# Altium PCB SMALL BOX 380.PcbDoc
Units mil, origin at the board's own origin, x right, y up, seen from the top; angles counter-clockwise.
Board outline 6000 x 4000 mil, 2 copper layers (Top Layer, Bottom Layer); 64 components, 32 nets, 216 pads, 52 vias.
Unrouted connection lines stored in the file: 8.
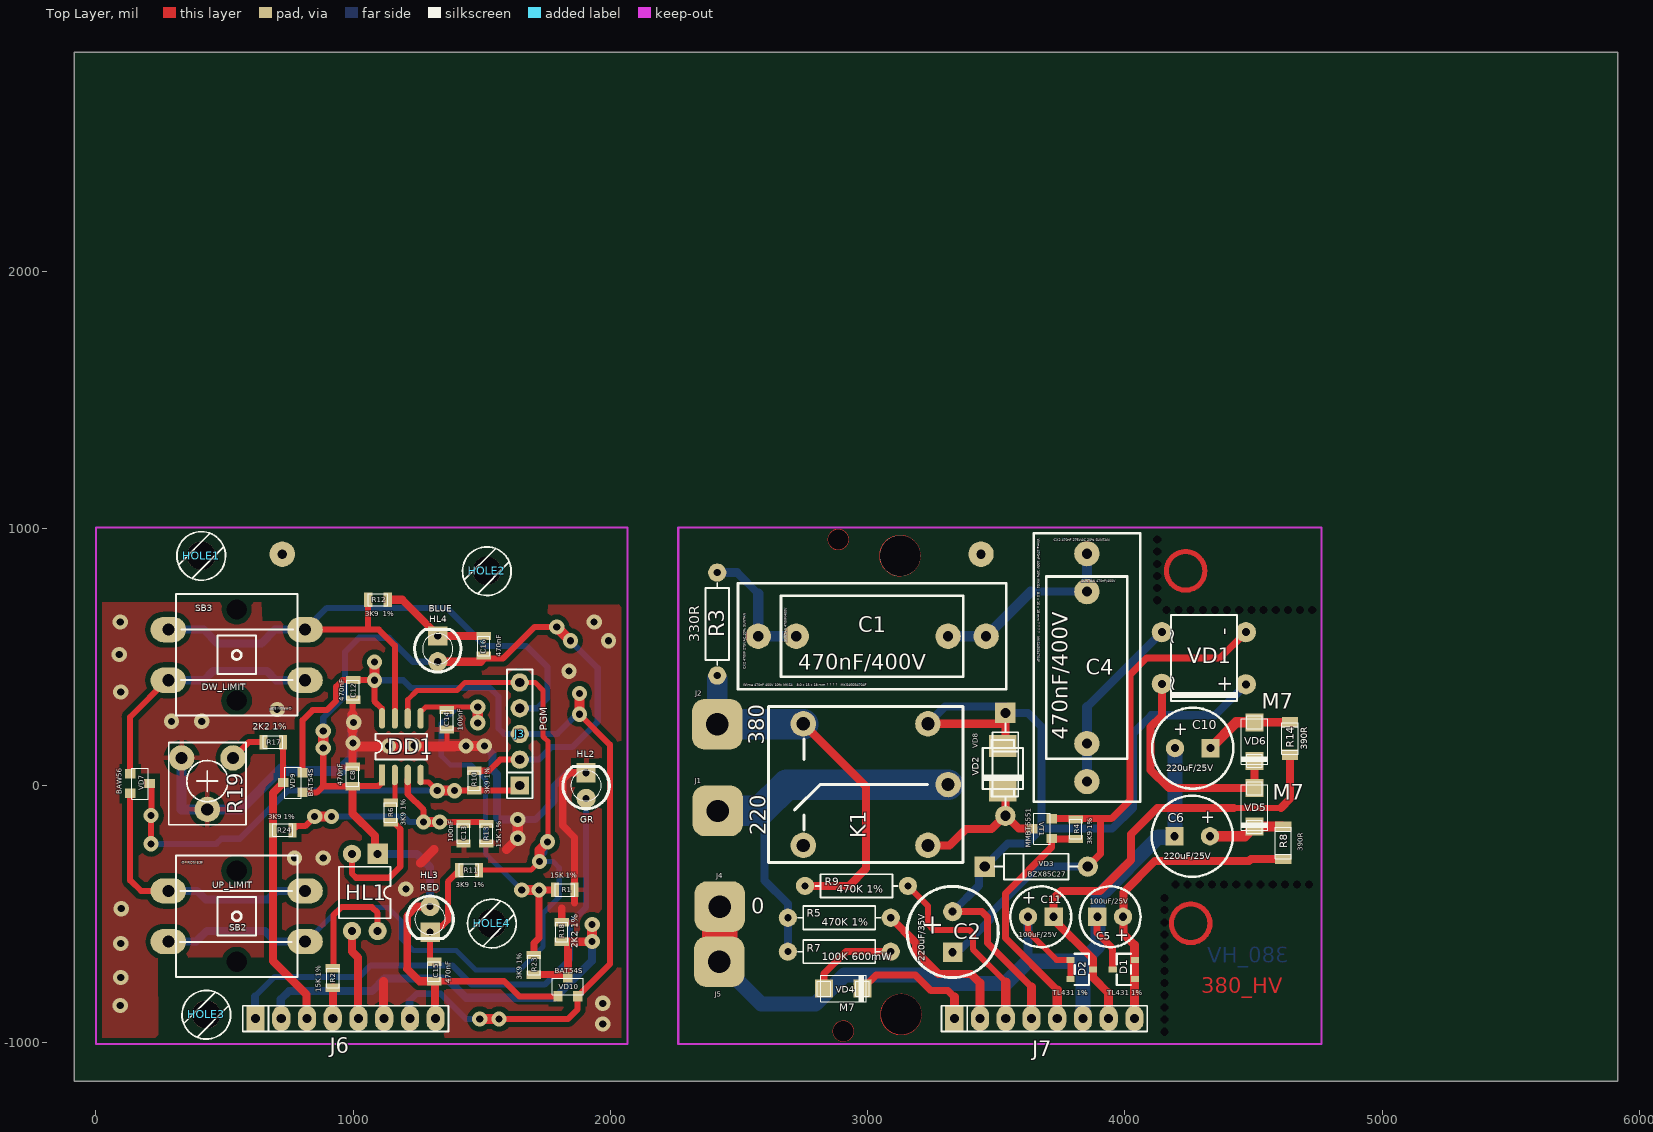
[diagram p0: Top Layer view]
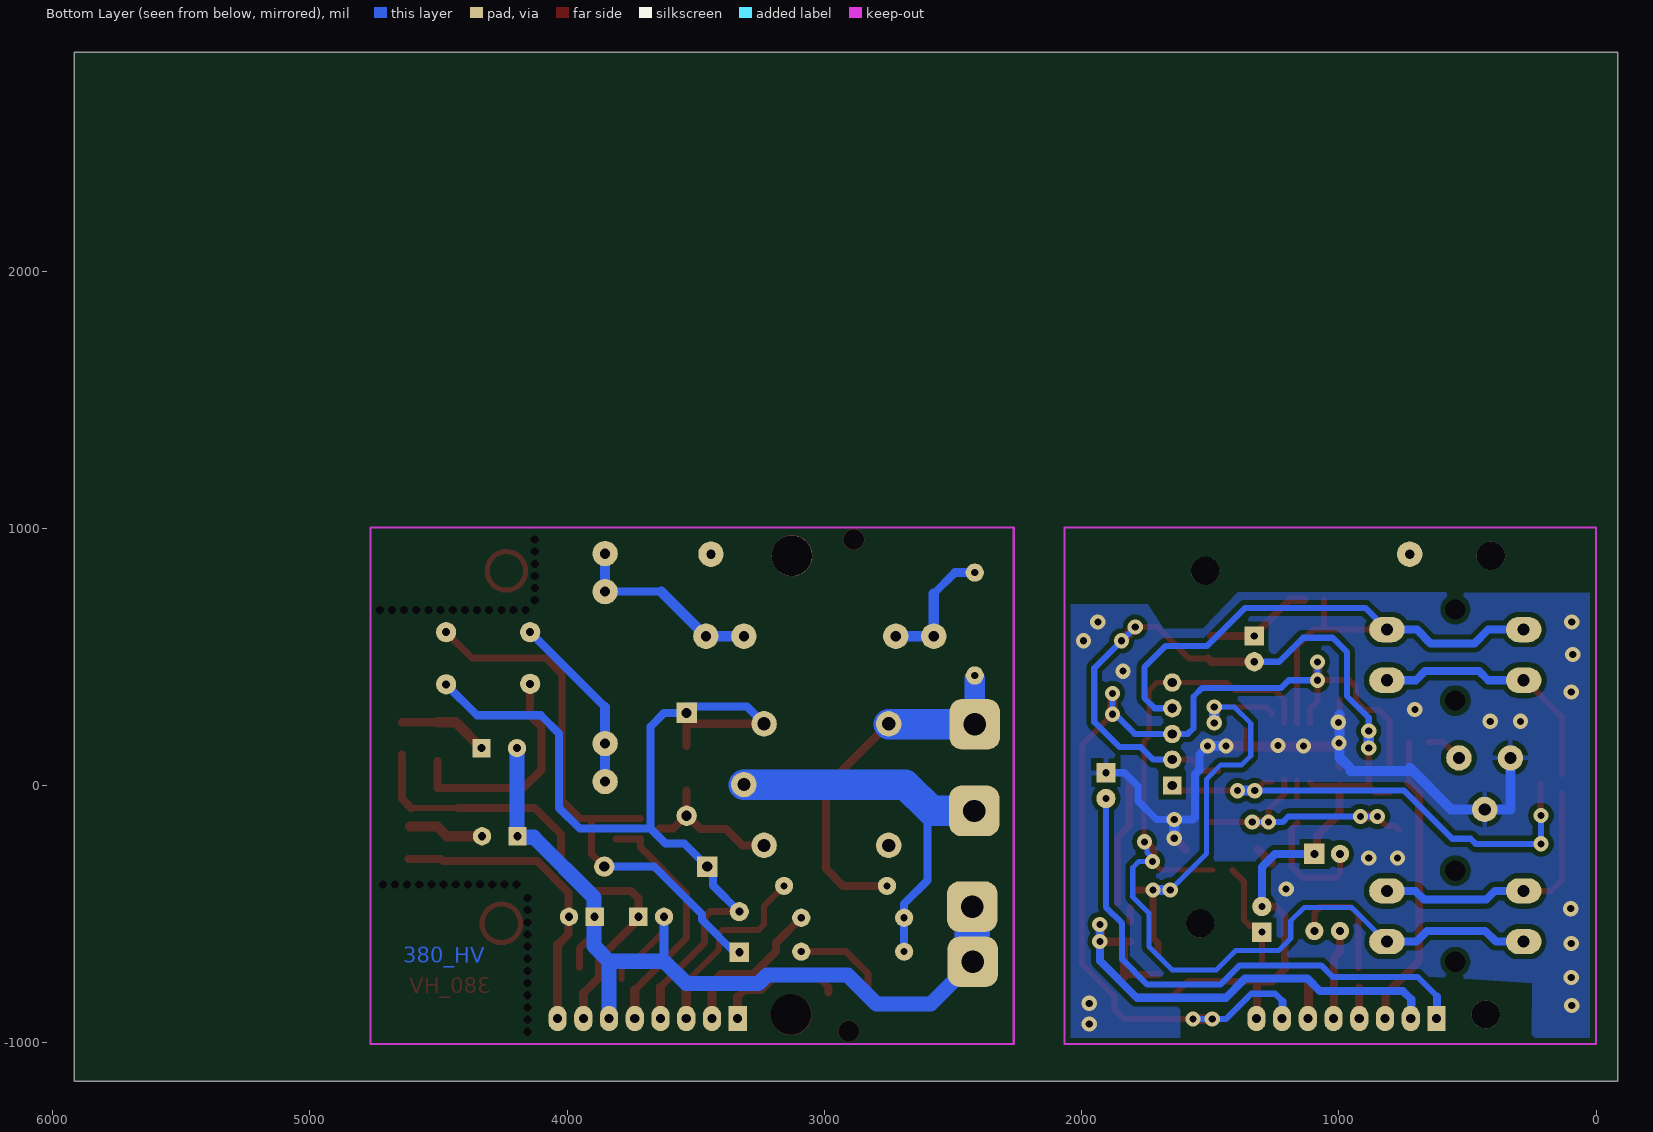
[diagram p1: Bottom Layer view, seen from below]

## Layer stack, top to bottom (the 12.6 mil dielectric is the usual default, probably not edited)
Top Layer: signal copper 1.4
Dielectric: dielectric 12.6, FR-4, Dk 4.8
Bottom Layer: signal copper 1.4

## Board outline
-84.06,-1149.25 5915.94,-1149.25 5915.94,2850.75 -84.06,2850.75

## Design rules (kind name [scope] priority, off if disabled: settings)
Clearance [All] p1: gap=19.68
ComponentClearance [All] p1: gap=15.75 collisioncheckmode=3 verticalgap=10 showdistances=TRUE
HoleSize [All] p1: absolutevalues=TRUE maxlimit=177.17 minlimit=27.56 maxpercent=80.000 minpercent=20.000
HoleToHoleClearance [All] p1: gap=15.75 allowstackedmicrovias=FALSE
PlaneConnect [All] p1: planeconnectstyle=Relief reliefexpansion=20 reliefentries=4 reliefconductorwidth=19.68 reliefairgap=10
PolygonConnect PolygonConnect_Vias [All vs isVia] p1: connectstyle=Direct reliefconductorwidth=13.78 reliefentries=4 polygonreliefangle="90 Angle"
PolygonConnect [All] p2: connectstyle=Relief reliefconductorwidth=19.68 reliefentries=4 polygonreliefangle="90 Angle"
RoomDefinition "SMALL BOX 380" [InComponentClass('SMALL BOX 380')] p1: confinementstyle=ConfineOut formatcopy=TRUE lockcomponents=FALSE outline -59.06,-1023.62 23.62,-1023.62 23.62,-1047.24 -59.06,-1047.24
RoutingVias [All] p1: holewidth=31.5 width=62.99 viastyle="Through Hole" minholewidth=27.56 minwidth=59.06 maxholewidth=35.43 maxwidth=66.93
SilkToSilkClearance [All] p1 off: silktosilkclearance=10
SilkscreenOverComponentPads [All] p1 off: minsilkscreentomaskgap=10
SolderMaskExpansion [All] p1: expansion=4
Width [All] p1: maxlimit=196.85 minlimit=19.68 preferedwidth=19.68 minimp=50.000000 maximp=50.000000 favimp=50.000000
22 further rules are at their usual default settings.

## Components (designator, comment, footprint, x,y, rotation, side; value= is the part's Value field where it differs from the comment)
C1 "470nF/400V" "C RM15+22,5" 3017.72,580.71 r0 top
C2 "220uF/35V" C_POL9X4 3330.71,-568.9 r270 top
C4 "470nF/400V" "C RM15+22,5" 3852.36,458.66 r270 top
C5 "100uF/25V" C_POL_6 3942.91,-509.84 r180 top
C6 "220uF/25V" C_POL_8 4261.81,-196.85 r180 top
C8 "470nF" 0805_STS 998.03,35.43 r90 top
C10 "220uF/25V" C_POL_8 4263.78,145.67 r0 top
C11 "100uF/25V" C_POL_6 3673.23,-509.84 r0 top
C12 "470nF" 0805_STS 1000,372.05 r90 top
C13 "100nF" 0805_STS 1429.13,-187.01 r270 top
C14 "100nF" 0805_STS 1364.17,255.91 r270 top
C15 "470nF" 0805_STS 1314.96,-722.44 r90 top
C16 "470nF" 0805_STS 1507.87,543.31 r90 top
D1 "TL431 1%" SOT-23 3996.06,-714.57 r90 top
D2 "TL431 1%" SOT-23 3832.68,-714.57 r270 top
DD1 "PIC12F1822_380_protect_1" SO-8 1112.2,41.34 r90 top
HL1 "OPTO 4" DIP4 1045.28,-415.35 r180 top
HL2 "GR" LED3 1905.51,0 r90 top
HL3 "RED" LED3 1299.21,-519.68 r270 top locked
HL4 "BLUE" LED3 1328.74,531.5 r90 top locked
HOLE1 "2,8" HOLE2,8 409.45,893.7 r0 top locked
HOLE2 "2,8" HOLE2,8 1519.69,834.65 r0 top locked
HOLE3 "2,8" HOLE2,8 429.13,-889.76 r0 top locked
HOLE4 "2,8" HOLE2,8 1539.37,-535.43 r0 top locked
J1 "220" PAD2,2 2417.32,-98.43 r0 top
J2 "380" PAD2,2 2415.35,238.19 r0 top
J3 "PGM" SIP5 1647.64,200.79 r90 top
J4 "0" PAD2,2 2425.2,-470.47 r0 top
J5 "0" PAD2,2 2423.23,-685.04 r0 top
J6 "CON8" SIP8 970.47,-905.51 r0 top locked
J7 "CON8" SIP8 3687.01,-905.51 r0 top locked
K1 "RAS24" "UNI 10A" 2992.13,3.94 r180 top
R1 "15K 1%" 0805_STS 1822.83,-405.51 r180 top
R2 "15K 1%" 0805_STS 921.26,-748.03 r270 top
R3 "330R" R1/4 2415.35,627.95 r90 top
R4 "3K9 1%" 0805_STS 3809.06,-169.29 r270 top
R5 "470K 1%" R1/4 2889.76,-513.78 r0 top
R6 "3K9 1%" 0805_STS 1145.67,-104.33 r270 top
R7 "100K 600mW" R1/4 2889.76,-645.67 r0 top
R8 "390R" 1206_STS 4616.14,-222.44 r270 top
R9 "470K 1%" R1/4 2956.69,-389.76 r0 top
R10 "3K9 1%" 0805_STS 1470.47,19.68 r90 top
R11 "3K9  1%" 0805_STS 1450.79,-328.74 r0 top
R12 "3K9  1%" 0805_STS 1096.46,722.44 r180 top
R13 "15K 1%" 0805_STS 1517.72,-187.01 r90 top
R14 "390R" 1206_STS 4641.73,183.07 r270 top
R17 "2K2 1%" 0805_STS 688.98,169.29 r180 top
R18 "2K2 1%" 0805_STS 1811.02,-568.9 r270 top
R19 "220R" RT_7.5X5_2 433.07,-92.52 r90 top
R23 "3K9 1%" 0805_STS 1702.76,-696.85 r270 top
R24 "3K9 1%" 0805_STS 726.38,-173.23 r180 top
SB2 "UP_LIMIT" "BTN BIG OMRON B3F" 547.24,-507.87 r0 top locked
SB3 "DW_LIMIT" "BTN BIG OMRON B3F" 547.24,507.87 r180 top locked
VD1 "BRIDGE SQ" "BRIDGE SQ TH" 4307.09,496.06 r270 top
VD2 "SMAJ 50V" SMB 3525.59,66.93 r270 top
VD3 "BZX85C27" 1N4004 3655.51,-314.96 r180 top
VD4 "M7" SMA 2905.51,-789.37 r0 top
VD5 "M7" SMA 4503.94,-84.65 r270 top
VD6 "M7" SMA 4503.94,171.26 r270 top
VD7 "BAW56" SOT-23-STS 171.26,7.87 r270 top
VD8 "P6KE" 1N4004 3535.43,82.68 r90 top
VD9 "BAT54S" SOT-23-STS 765.75,11.81 r90 top
VD10 "BAT54S" SOT-23-STS 1834.65,-781.5 r0 top
VT1 "MMBT5551" SOT-23-STS 3677.17,-167.32 r90 top

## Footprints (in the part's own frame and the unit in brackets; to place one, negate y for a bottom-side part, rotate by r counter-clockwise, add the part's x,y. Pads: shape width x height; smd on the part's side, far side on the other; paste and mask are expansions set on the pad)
1N4004 [mil]
  round 79 hole 39.37: 1(-200,0)
  rect 79x79 hole 39.37: 2(200,0)
  silkscreen extent -160,-50 160,50
0805_STS [mil]
  rect 32x56 smd: 1(-38,0) 2(38,0)
  silkscreen extent -38,-24 38,24
1206_STS [mm]
  rect 1x1.6 smd: 1(-1.6,0) 2(1.6,0)
  silkscreen extent -1.55,-0.8 1.55,0.8
"BRIDGE SQ TH" [mm] "DFxx DB10x"
  round 2 hole 0.8: 1(-2.55,-4.15) 2(2.55,-4.15) 3(2.6,4.15) 4(-2.55,4.15)
  silkscreen extent -4.25,-3.25 4.25,3.25
"BTN BIG OMRON B3F" [mm] "От китайската дефектнотокова"
  round 1.524 hole 2: 0(0,-4.5) 0(0,4.5)
  oval 3.5x2.5 hole 1.2: 1(-6.75,2.5) 1'(6.75,2.5) 2(-6.75,-2.5) 2'(6.75,-2.5)
  silkscreen extent -6,-6 6,6
"C RM15+22,5" [mm] "За 2 кондензатора с растер 15 и 22,5мм"
  round 2.5 hole 1: 1(-11.25,0) 1'(-7.5,0) 2(7.5,0) 2'(11.25,0)
  silkscreen extent -13.25,-5.25 13.25,5.25
C_POL9X4 [mm]
  round 1.9 hole 0.8: 1(-2,0)
  rect 1.9x1.9 hole 0.8: 2(2,0)
  silkscreen extent -4.5,-4.5 4.5,4.5
C_POL_6 [mil]
  round 71 hole 31.5: 1(-50,0)
  rect 71x71 hole 31.5: 2(50,0)
  silkscreen extent -118,-118 118,118
C_POL_8 [mil]
  round 71 hole 31.5: 1(-68.9,0)
  rect 71x71 hole 31.5: 2(68.9,0)
  silkscreen extent -157,-157 157,157
DIP4 [mil]
  rect 79x79 hole 31.5: 1(-50,-150)
  round 71 hole 31.5: 2(50,-150) 3(50,150) 4(-50,150)
  silkscreen extent -100,-100 100,100
HOLE2,8 [mm] "ЗА защитата"
  round 2.8 hole 2.8 unplated: ""(0,0)
  silkscreen extent -2.4,-2.43 2.4,2.37
LED3 [mm]
  round 1.905 hole 0.7: 1(-1.27,0)
  rect 1.905x1.905 hole 0.7: 2(1.27,0)
  silkscreen extent -2.29,-2.29 1.91,2.29
PAD2,2 [mm] "За многожилна жица"
  rrect50% 5x5 hole 2.2: 1(0,0)
R1/4 [mm]
  round 1.8 hole 0.7: 1(-5.08,0) 2(5.08,0)
  silkscreen extent -4.06,-1.15 4.06,1.15
RT_7.5X5_2 [mil]
  round 99 hole 47.24: 1(200,-100) 2(0,0) 3(200,100)
  silkscreen extent -60,-150 260,150
SIP5 [mil]
  rect 71x71 hole 35.43: 1(-200,0)
  round 71 hole 35.43: 2(-100,0) 3(0,0) 4(100,0) 5(200,0)
  silkscreen extent -250,-50 250,50
SIP8 [mm]
  rect 1.8x2.5 hole 0.9: 1(-8.89,0)
  oval 1.8x2.5 hole 0.9: 2(-6.35,0) 3(-3.81,0) 4(-1.27,0) 5(1.27,0) 6(3.81,0) 7(6.35,0) 8(8.89,0)
  silkscreen extent -10.16,-1.27 10.16,1.27
SMA [mil]
  rect 70x70 smd: 1(-75,0) 2(75,0)
  silkscreen extent -100,-52 100,51
SMB [mil]
  rect 85x108 smd: 1(-87,0) 2(87,0)
  silkscreen extent -110,-79 110,78
SO-8 [mil]
  rect 80x24 smd: 1(0,0)
  oval 80x24 smd: 2(0,-50) 3(0,-100) 4(0,-150) 5(220,-150) 6(220,-100) 7(220,-50) 8(220,0)
  silkscreen extent 60,-175 160,25
SOT-23 [mm]
  rect 0.6x0.8 smd: 1(-0.95,-1.1) 2(0.95,-1.1) 3(0,1.1)
  silkscreen extent -1.55,-0.7 1.55,0.7
SOT-23-STS [mil]
  rect 36x41 smd: 1(-38,-38) 2(38,-38) 3(0,37)
  silkscreen extent -60,-32 60,32
"UNI 10A" [mm]
  round 2.515 hole 1.3: 1(-8.15,0) 2(6.15,6) 3(6.15,-6) 4(-6.15,6) 5(-6.15,-6)
  silkscreen extent -9.6,-7.7 9.6,7.7

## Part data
C1 C4: library part "C RM15+22,5"
C2 C5 C6 C10 C11: library part C-POL
C8 C12 C13 C14 C15 C16: library part C-SMD
D1 D2: library part D_ZR431, "Reference Zener Diode"
HL2 HL3 HL4: library part LED
HOLE1 HOLE2 HOLE3 HOLE4: library part HOLE
J1 J2 J4 J5: library part CON1
J3: library part CON5
K1: library part "RELAY 1GR"
R1 R2 R4 R6 R8 R10 R11 R12 R13 R14 R18 R23 R24: library part R-SMD
R3 R5 R7 R9 R17: library part R1/4
R19: library part R-TRIM
SB2 SB3: library part "SW-BUTTON A"
VD2 VD8: library part SIBAR
VD3: library part "DIODE ZENER"
VD4 VD5 VD6: library part DIODE-SMD
VD7: library part DIODE-CA
VD9 VD10: library part DIODE-DBL
VT1: library part NPN-SMD

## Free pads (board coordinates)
  round 98.43 hole 35.43: 0(724.41,899.61) 0(3440.95,899.61)
  round 157.48 hole 157.48: 0(3125.98,893.7)
  round 60 hole 157.48: 1(3129.92,-889.76)
  round 0 hole 31.5: 22(4125.98,720.47) 22(4125.98,767.72) 22(4125.98,814.96) 22(4125.98,862.2) 22(4125.98,909.45) 22(4125.98,956.69) 22(4153.54,-956.69) 22(4153.54,-909.45) 22(4153.54,-862.2) 22(4153.54,-814.96) 22(4153.54,-767.72) 22(4153.54,-720.47) 22(4153.54,-673.23) 22(4153.54,-625.98) 22(4153.54,-578.74) 22(4153.54,-531.5) 22(4153.54,-484.25) 22(4153.54,-437.01) 22(4161.42,683.07) 22(4196.85,-383.86) 22(4208.66,683.07) 22(4244.09,-383.86) 22(4255.91,683.07) 22(4291.34,-383.86) 22(4303.15,683.07) 22(4338.58,-383.86) 22(4350.39,683.07) 22(4385.83,-383.86) 22(4397.64,683.07) 22(4433.07,-383.86) 22(4444.88,683.07) 22(4480.32,-383.86) 22(4492.13,683.07) 22(4527.56,-383.86) 22(4539.37,683.07) 22(4574.8,-383.86) 22(4586.61,683.07) 22(4622.05,-383.86) 22(4633.86,683.07) 22(4669.29,-383.86) 22(4681.1,683.07) 22(4716.54,-383.86) 23(4728.35,683.07)
  round 0 hole 78.74: 53(2885.83,956.69) 53(2905.51,-954.72)

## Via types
v1: diameter 59.06, hole 27.56, Top Layer to Bottom Layer, tented both sides, 52 vias

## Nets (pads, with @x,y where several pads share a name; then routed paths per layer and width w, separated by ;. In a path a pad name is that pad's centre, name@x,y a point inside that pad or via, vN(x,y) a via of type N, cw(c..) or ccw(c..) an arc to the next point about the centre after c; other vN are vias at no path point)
220: J1.1 K1.1 R5.1 R7.1 | length 1534.6
  Bottom Layer w31.5: 2599.21,-86.61 2599.21,-368.9 2689.76,-459.45 R7.1
  Bottom Layer w118.11: J1.1 2582.68,-98.43 2685.04,3.94 K1.1
380: J2.1 K1.3 R3.1 R9.1 | length 1441.8
  Top Layer w31.5: K1.3 2994.09,-3.94 2994.09,-322.83 2927.17,-389.76 R9.1
  Bottom Layer w78.74: J2.1 R3.1@2415.35,416.14
  Bottom Layer w118.11: J2.1 K1.3@2750,238.19
C2*1: C2.1 J6.4 J7.4 K1.5 R2.2 VD1.3 VD2.1 VD3.2 VD8.2 | length 3777.4
  Top Layer w27.56: C2.1 3444.88,-490.16 3466.54,-511.81 3466.54,-612.2 3637.01,-782.68
  Top Layer w31.5: J6.4@921.26,-906.88 R2.2@921.26,-785.43 ; K1.5@3234.64,240.54 3535.43,240.54 ; VD2.1@3535.43,153.93 3535.43,240.54 ; VD8.2@3535.43,306.3 3535.43,240.54
  Top Layer w35.43: J7.4 3637.01,-782.68
  Bottom Layer w31.5: K1.5 3301.18,307.09 VD8.2@3535.43,307.09 ; C2.1 3433.07,-387.8 3433.07,-337.4 VD3.2 3544.69,-225.79 ; VD8.2 3622.83,282.68 3675.2,230.32 3675.2,-167.32 3950.79,-167.32 4031.5,-86.61 4031.5,202.76 4102.36,273.62 4350.39,273.62 VD1.3 ; 3545.28,-225.79 3618.11,-225.79 3676.57,-167.32
GND: C5.2 C6.2 C8.2 C10.1 C11.1 C12.1 C13.2 C14.2 D1.3 D2.1 D2.2 HL2.2 J4.1 J5.1 J6.6 J7.6 R1.1 R13.1 R18.1 R19.2 R19.3 | length 7850.1
  Top Layer w19.68: 1364.17,153.54 C14.2
  Top Layer w23.62: 998.03,275.59 C12.1@998.03,334.05 ; C11.1 3623.23,-566.14 3734.25,-677.17 D2.1 D2.2
  Top Layer w27.56: R18.1 1811.02,-476.38 ; 1860.83,-455.24 R1.1 1860.83,-201.39 1814.96,-155.51 1814.96,23.62 1841.34,50 HL2.2 ; C5.2@3891.73,-507.87 3891.73,-572.83 3952.76,-633.86 D1.3@3952.76,-706.69
  Top Layer w31.5: C8.2 998.03,151.57 998.03,214.57
  Top Layer w35.43: J6.6@1118.5,-907.48 1118.5,-761.42 ; 1261.81,-301.18 1314.96,-248.03 ; 1596.46,-248.03 v1(1639.76,-204.72)
  Top Layer w39.37: v1@998.03,151.57 1391.73,151.57 ; 998.03,214.57 998.03,275.59 ; 1364.17,153.54 v1(1509.84,153.54) ; v1(1639.76,-204.72) v1(1639.76,-131.89)
  Top Layer w137.8: J5.1@2425.2,-671.26 J4.1
  Bottom Layer w27.56: v1(1639.76,-131.89) 1708.66,-131.89 1781.5,-59.06 1781.5,-1.97 1833.46,50 HL2.2
  Bottom Layer w31.5: v1(1509.84,153.54) 1541.34,122.05 1541.34,62.06 1559.06,44.34 1559.06,-124.02 1566.93,-131.89 v1(1639.76,-131.89)
  Bottom Layer w35.43: 3623.62,-682.68 C11.1@3623.62,-509.84
  Bottom Layer w39.37: R19.3 333.07,-92.52 R19.2 562.99,-92.52 724.41,68.9 ; 722.44,57.09 954.72,57.09 ; 956.69,68.9 998.03,110.24 998.03,275.59 ; v1(1438.98,153.54) v1(1509.84,153.54) ; v1(1639.76,-204.72) v1(1639.76,-131.89)
  Bottom Layer w59.06: J5.1@2425.2,-687.01 2586.61,-848.43 2797.24,-848.43 2909.45,-736.22 3222.44,-736.22 3255.91,-769.68 3536.61,-769.68 3623.62,-682.68 3837.01,-682.68 ; J7.6 3837.01,-682.68 ; C6.2@4192.91,-200.79 4129.92,-200.79 3895.67,-435.04 3895.67,-624.02 3837.01,-682.68 ; C6.2@4194.88,-194.88 C10.1
  Bottom Layer w137.8: J5.1@2425.2,-687.01 J4.1
  other v1: 1970.47,-927.17 94.49,-854.33 1970.47,-846.46 96.46,-746.06 96.46,-614.17 98.43,-478.35 1204.72,-401.57 771.65,-281.5 883.86,-281.5 1137.8,153.54 1236.22,155.51 1000,165.35 1001.97,246.06 293.31,250 411.42,250 704.72,295.28 96.46,364.17 1838.58,444.88 90.55,509.84 1992.13,562.99 94.49,635.83 1937.01,635.83
HL1*3: HL1.3 J6.5 J7.5 R4.2 VT1.1 | length 1287.8
  Top Layer w27.56: VT1.1 3715.17,-239.56 3535.43,-419.29 3535.43,-592.52 3737.01,-794.09 ; VT1.1@3730.91,-207.29 R4.2
  Top Layer w31.5: HL1.3 995.28,-644.88 1018.9,-668.5 J6.5@1018.9,-907.09
  Top Layer w35.43: J7.5 3737.01,-794.09
HL2*1: HL2.1 J6.1 J7.1 VD4.2 | length 2595.4
  Top Layer w27.56: VD4.2@2984.45,-785.24 3033.46,-736.22 3185.04,-736.22 3246.06,-797.24 3312.99,-797.24 3337.01,-821.26
  Top Layer w31.5: VD4.2@2984.45,-803.15 VD4.2@2984.45,-785.24
  Top Layer w35.43: J7.1 3337.01,-821.26
  Bottom Layer w23.62: 618.5,-819.29 693.7,-744.09 1023.62,-744.09 1068.9,-698.82 1385.83,-698.82 1460.63,-773.62 1744.09,-773.62 1842.52,-675.2 1842.52,-535.43 1905.51,-472.44 HL2.1
  Bottom Layer w31.5: J6.1@618.5,-907.48 618.5,-819.29
NetC1_1: C1.1 C1.1' R3.2 | length 506.4
  Bottom Layer w31.5: 2492.91,827.95 2574.8,746.06
  Bottom Layer w35.43: R3.2 2492.91,827.95
  Bottom Layer w39.37: 2574.8,746.06 C1.1 C1.1'
NetC1_2: C1.2 C1.2' C4.1 C4.1' | length 758.8
  Bottom Layer w31.5: 3633.86,753.94 C4.1'
  Bottom Layer w39.37: C1.2 C1.2' 3633.86,753.94 ; C4.1' C4.1
NetC2_2: C2.2 R4.1 VD1.4 VD3.1 VT1.2 | length 2235.4
  Top Layer w27.56: VT1.2@3715.17,-127.95 3948.82,-127.95 4019.69,-57.09 4019.69,431.1 4084.65,496.06 4370.08,496.06 VD1.4 ; VD3.1 3905.51,-264.96 3905.51,-127.95
  Top Layer w31.5: VD3.1 VD3.1@3855.51,-303.94
  Bottom Layer w31.5: C2.2 3350.39,-647.64 3476.38,-521.65 3476.38,-500 3661.42,-314.96 VD3.1
NetC4_2: C4.2 C4.2' VD1.1 | length 701.4
  Bottom Layer w31.5: 3852.36,305.12 VD1.1
  Bottom Layer w39.37: C4.2' C4.2 3852.36,305.12
NetC6_1: C6.1 R8.1 VD5.2 | length 294.7
  Top Layer w39.37: C6.1 4466.73,-196.85 VD5.2 R8.1@4610.04,-159.65
NetC10_2: C10.2 R14.1 VD6.1 | length 350.7
  Top Layer w31.5: VD6.1 R14.1@4641.73,246.26
  Top Layer w39.37: C10.2 4433.27,246.26 VD6.1
NetC13_1: C13.1 DD1.3 R13.2 R24.1 | length 1087.3
  Top Layer w23.62: R24.1 780.13,-157.48 812.99,-157.48 v1(850.39,-120.08) ; DD1.3@1212.2,23.62 1212.2,-33.07 1273.62,-94.49 v1(1273.62,-141.73) ; v1(1336.61,-141.73) R13.2@1501.97,-141.73
  Top Layer w39.37: v1(850.39,-120.08) v1(915.35,-120.08) ; v1(1273.62,-141.73) v1(1336.61,-141.73)
  Bottom Layer w23.62: v1(850.39,-120.08) 1196.85,-120.08 1218.5,-141.73 v1(1273.62,-141.73) v1(1336.61,-141.73)
NetC14_1: C14.1 DD1.5 R1.2 R23.1 | length 1814.6
  Top Layer w19.68: DD1.5@1261.81,273.62 1261.81,285.43 1281.5,305.12 v1(1484.25,305.12)
  Top Layer w27.56: R23.1 1702.76,-612.2 1722.44,-592.52 v1(1722.44,-405.51) R1.2
  Top Layer w39.37: v1(1484.25,244.09) v1(1484.25,305.12) ; v1(1655.51,-405.51) v1(1722.44,-405.51)
  Bottom Layer w19.68: v1(1484.25,305.12) 1405.51,305.12 1342.52,242.13 1342.52,116.14 1377.95,80.71 1458.66,80.71 1513.78,25.59 1513.78,-263.78 v1(1655.51,-405.51)
  Bottom Layer w39.37: v1(1484.25,244.09) v1(1484.25,305.12) ; v1(1655.51,-405.51) v1(1722.44,-405.51)
NetC15_2: C15.2 HL3.2 R11.1 | length 402.9
  Top Layer w23.62: C15.2@1299.21,-678.54 HL3.2 ; HL3.2@1318.9,-545.28 1346.46,-545.28 1368.21,-523.52 1368.21,-441.11 1368.11,-441.01 1368.11,-374.02 R11.1@1397.64,-344.49 ; R11.1 1397.64,-343.89 R11.1@1397.64,-344.49 ; R11.1@1414.07,-330.02 1399.61,-344.49 R11.1@1397.64,-344.49
NetC16_2: C16.2 HL4.2 R12.1 | length 424.4
  Top Layer w31.5: R12.1 1190.95,722.44 1330.71,582.68 HL4.2@1327.56,582.68 ; HL4.2 C16.2@1495.87,581.5
NetDD1_2: DD1.2 R6.1 | length 73.4
  Top Layer w19.68: 1162.2,-49.8 DD1.2@1162.2,23.62
NetHL1_2: HL1.2 R6.2 | length 466.6
  Top Layer w23.62: HL1.2 995.28,-341.73 1011.81,-358.27 1139.76,-358.27 1183.07,-314.96 1183.07,-167.92 R6.2@1161.42,-146.27
NetHL1_4: HL1.4 R2.1 | length 469.6
  Top Layer w23.62: R2.1@923.23,-708.66 923.23,-503.94 954.72,-472.44 1072.83,-472.44 1095.28,-494.88 HL1.4
NetK1_4: K1.4 VD2.2 VD8.1 VT1.3 | length 571.2
  Top Layer w31.5: K1.4 3318.9,-232.28 3381.89,-169.29 3481.5,-169.29 VD8.1@3535.43,-115.35 ; VD2.2@3535.43,-20.07 VD8.1@3535.43,-115.35 ; VT1.3 3587.4,-167.32 VD8.1@3535.43,-115.35
NetR7_2: R7.2 VD4.1 | length 353.3
  Top Layer w27.56: VD4.1 2830.51,-730.51 2915.35,-645.67 R7.2
NetR17_2: R17.2 R19.1 | length 143.5
  Top Layer w23.62: R19.1 594.88,169.29 R17.2
NetSB2_1: SB2.1 SB2.1' VD7.2 | length 1062.4
  Top Layer w23.62: 133.26,-368.11 VD7.2 ; 133.56,-367.81 175.2,-409.45 SB2.1
  Bottom Layer w31.5: SB2.1 393.7,-409.45 427.17,-442.91 669.29,-442.91 702.76,-409.45 SB2.1'
NetSB3_1: SB3.1 SB3.1' VD7.1 | length 991.3
  Top Layer w23.62: 132.57,266.43 SB3.1'@281.5,415.35 ; VD7.1 133.26,265.75
  Bottom Layer w31.5: SB3.1' 419.29,409.45 454.72,444.88 665.35,444.88 700.79,409.45 SB3.1
NetVD1_2: VD1.2 VD5.1 VD6.2 | length 891.3
  Top Layer w31.5: VD1.2 4143.7,271.65 4100.39,228.35 4100.39,61.02 4171.06,-9.65 VD5.1 VD6.2
PGC: DD1.6 J3.5 R11.2 SB2.2 SB2.2' | length 3793.9
  Top Layer w19.68: DD1.6@1212.2,243.62 1212.2,334.25 1248.03,370.08 1403.54,370.08 1434.25,400.79 J3.5 1707.48,400.79 1738.19,370.08 1738.19,190.94 1756.69,172.44 v1@1756.69,-218.5 ; R11.2 1690.94,-328.74 v1(1724.41,-295.28)
  Top Layer w39.37: v1(1724.41,-295.28) 1724.41,-250 v1(1755.91,-218.5)
  Bottom Layer w19.68: SB2.2'@836.61,-586.61 948.82,-474.41 1135.83,-474.41 1187.01,-525.59 1187.01,-594.49 1234.25,-641.73 1401.57,-641.73 1476.38,-716.54 1647.64,-716.54 1738.19,-625.98 1738.19,-496.06 1801.18,-433.07 1801.18,-318.9 1777.56,-295.28 v1(1724.41,-295.28) 1724.41,-281.5 1746.06,-259.84 1746.06,-228.35 v1(1755.91,-218.5)
  Bottom Layer w31.5: SB2.2 389.76,-606.3 431.1,-564.96 657.48,-564.96 698.82,-606.3 SB2.2'
PGD: DD1.7 J3.4 R12.2 SB3.2 SB3.2' | length 2681.3
  Top Layer w23.62: SB3.2 1099.8,606.3 1162.2,543.89 DD1.7@1162.2,243.62 ; 1058.46,610.24 R12.2
  Bottom Layer w23.62: SB3.2 897.64,690.94 1364.17,690.94 1511.81,543.31 1673.23,543.31 1755.91,460.63 1755.91,340.55 1716.14,300.79 J3.4
  Bottom Layer w31.5: SB3.2' 419.29,606.3 472.44,553.15 643.7,553.15 696.85,606.3 SB3.2
R5*2: J6.2 J7.2 R5.2 R18.2 R23.2 VD10.3 | length 2618.6
  Top Layer w27.56: R23.2 VD10.3@1834.65,-734.85 ; v1@1927.17,-606.9 v1@1927.17,-606.3
  Top Layer w31.5: R18.2 1927.17,-606.9 1928.54,-606.9 v1(1929.13,-606.3) ; VD10.3@1834.65,-746.66 R18.2@1834.65,-608.27 ; R5.2 3188.19,-612.2 3188.19,-644.88 3275.59,-732.28 3401.58,-732.28 3437.01,-767.72
  Top Layer w35.43: J7.2 3437.01,-767.72
  Top Layer w39.37: v1(1929.13,-606.3) v1(1929.13,-539.37)
  Bottom Layer w31.5: J6.2@718.5,-907.48 718.5,-830.71 750,-799.21 1072.83,-799.21 1122.05,-750 1364.17,-750 1438.98,-824.8 1785.43,-824.8 1929.13,-681.1 v1(1929.13,-606.3) v1(1929.13,-539.37)
R9*2: J6.3 J7.3 R9.2 R17.1 R24.2 VD9.3 | length 1902.2
  Top Layer w23.62: VD9.3@726.98,11.81 R17.1 ; R9.2 3235.43,-468.5 3235.43,-539.37 ; 3234.84,-539.96 3255.91,-561.02 3395.67,-561.02 3409.45,-574.8 3409.45,-635.83 3537.01,-763.39
  Top Layer w31.5: VD9.3 688.38,-28.56 688.38,-682.47 818.5,-812.6 J6.3@818.5,-907.48
  Top Layer w35.43: J7.3 3537.01,-763.39
VDD: C5.1 C8.1 C15.1 C16.1 D1.1 D1.2 DD1.1 HL1.1 HL3.1 HL4.1 J3.2 J6.8 J7.8 R8.2 R10.2 VD9.1 VD10.1 | length 5904.1
  Top Layer w23.62: VD9.1 857.67,-26.19 ; 860.24,-25.59 883.86,-1.97 ; 881.29,-2.57 C8.1 ; 883.86,-2.57 883.86,-1.97 ; v1(883.86,145.67) 883.86,-1.97 ; C8.1@1009.24,-1.97 1098.43,-1.97 DD1.1@1112.2,11.81 ; C15.1@1318.5,-760.44 1587.21,-760.44 1646.27,-819.5 VD10.1 ; R10.2 1528.16,57.68 1571.26,100.79 J3.2 ; C16.1@1507.87,493.5 1582.08,493.5 1704.72,616.14 v1(1791.34,616.14)
  Top Layer w27.56: 1210.34,-712.31 1210.34,-506.19 1246.85,-469.68
  Top Layer w31.5: C8.1 998.03,-108.27 1084.65,-194.88 1084.65,-196.85 1085.43,-197.64 HL1.1@1085.43,-265.35 ; 1210.34,-712.31 1258.47,-760.44 1318.5,-760.44 J6.8@1318.5,-907.48 ; 1246.85,-469.68 HL3.1 ; HL4.1 1495.87,481.5 C16.1@1507.87,493.5 ; 4037.01,-619.69 3994.09,-576.77 3994.09,-415.35 4116.14,-293.31 4482.28,-293.31 4490.16,-285.43 R8.2
  Top Layer w35.43: J7.8 4037.01,-619.69
  Top Layer w39.37: v1(883.86,145.67) v1(883.86,212.6) ; v1(1791.34,616.14) v1(1844.49,562.99)
  Bottom Layer w23.62: v1(883.86,212.6) 883.86,263.78 968.5,348.43 968.5,519.68 1023.62,574.8 1138.98,574.8 1232.28,481.5 HL4.1 ; J3.2 1720.87,100.79 1769.69,149.61 1852.36,149.61 1950.79,248.03 1950.79,456.69 v1(1844.49,562.99) v1(1791.34,616.14)
  Bottom Layer w31.5: HL1.1@1085.43,-265.35 1247.64,-265.35 1299.21,-316.93 HL3.1
  Bottom Layer w39.37: v1(883.86,145.67) v1(883.86,212.6)
VPP: DD1.4 J3.1 R10.1 VD7.3 | length 2020.7
  Top Layer w19.68: DD1.4@1259.84,13.78 1293.31,13.78 v1(1326.77,-19.68)
  Top Layer w23.62: v1(214.57,-226.38) v1(214.57,-116.14) ; v1@216.54,-88.58 VD7.3@216.54,7.87 ; v1(1393.7,-19.68) J3.1@1649.61,-19.68
  Top Layer w39.37: v1@1332.68,-19.68 v1@1401.57,-19.68
  Bottom Layer w23.62: v1(214.57,-116.14) v1(214.57,-226.38) 468.5,-226.38 488.19,-206.69 559.06,-206.69 746.06,-19.68 v1@1366.14,-19.68
  Bottom Layer w39.37: v1@1332.68,-19.68 v1(1393.7,-19.68)
VSS: C11.2 C12.2 D2.3 DD1.8 J3.3 J6.7 J7.7 R14.2 VD9.2 VD10.2 | length 6026.3
  Top Layer w23.62: VD9.2 803.75,254.54 842.52,293.31 897.64,293.31 933.67,329.34 933.67,384.46 959.26,410.05 C12.2 1078.14,410.05 v1@1082.68,414.58 ; v1(1082.68,409.45) 1082.68,328.74 1112.2,299.21 DD1.8@1112.2,243.62 ; v1(1566.93,-907.48) 1834.65,-907.48 1872.65,-869.48 VD10.2 1998.03,-694.11 1998.03,159.45 v1(1879.92,277.56) ; 4423.23,-86.61 4606.3,-86.61
  Top Layer w31.5: 3937.01,-807.09 3875.98,-746.06 3875.98,-673.23 3723.23,-520.47 C11.2 3722.44,-509.06 3722.44,-438.98 3751.97,-409.45 3903.54,-409.45 4023.62,-289.37 4023.62,-188.98 4125.98,-86.61 4423.23,-86.61 ; 4606.3,-86.61 4641.73,-51.18 R14.2
  Top Layer w35.43: J7.7 3937.01,-807.09
  Top Layer w39.37: v1@1082.68,414.58 v1(1082.68,480.32) ; v1(1492.13,-907.48) v1(1566.93,-907.48) ; v1(1879.92,277.56) v1(1879.92,358.27)
  Bottom Layer w23.62: v1(1082.68,480.32) v1(1082.68,409.45) 1194.88,409.45 1224.41,379.92 1531.5,379.92 1564.96,346.46 1564.96,222.44 1586.61,200.79 1793.31,200.79 1870.08,277.56 v1(1879.92,277.56) v1(1879.92,358.27) ; 1218.5,-838.58 1248.03,-809.06 1340.55,-809.06 1438.98,-907.48 v1(1492.13,-907.48) v1(1566.93,-907.48)
  Bottom Layer w31.5: J6.7@1218.5,-907.48 1218.5,-838.58
pads on no net: HOLE1. HOLE2. HOLE3. HOLE4. K1.2 SB2.0 SB3.0
copper on no net: | length 2226.3
  Top Layer w19.68: 2917.32,956.69 ccw(c2885.83,956.69) 2917.32,956.69 ; 2937.01,-954.72 ccw(c2905.51,-954.72) 2937.01,-954.72 ; 3196.85,893.7 ccw(c3125.98,893.7) 3196.85,893.7 ; 3200.76,-889.76 ccw(c3129.9,-889.76) 3200.76,-889.76 ; 4311.02,834.65 ccw(c4236.22,834.65) 4311.02,834.65 ; 4330.71,-535.43 ccw(c4255.91,-535.43) 4330.71,-535.43

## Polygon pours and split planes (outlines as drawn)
GND on Top Layer "GND" (solid, remove dead copper, pour order 2): 2066.93,-1003.94 2064.96,704.72 1757.87,702.76 1755.91,616.14 1332.68,614.17 1328.74,637.8 1110.24,635.83 913.39,635.83 913.39,637.8 645.67,639.76 643.7,712.6 -59.06,712.6 -59.06,-1003.94 242.13,-1003.94 240.16,-669.29 673.23,-667.32 675.2,-1007.87
GND on Bottom Layer "GND" (solid, remove dead copper, pour order 4): 2066.93,-1003.94 2066.93,704.72 1742.13,704.72 1681.1,610.24 1527.56,612.2 1393.7,751.97 1322.83,753.94 1021.65,751.97 301.18,750 -1.97,750 0,-1003.94 159.45,-1000 250,-1000 248.03,-767.72 1330.71,-700.79 1330.71,-610.24 1326.77,-295.28 1521.65,-293.31 1704.72,-454.72 1616.14,-767.72 1616.14,-1003.94

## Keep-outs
Keep-Out Layer:
  lines w7.87: 0,-1003.94 0,1003.94 2066.93,1003.94 2066.93,-1003.94 0,-1003.94 ; 2263.78,-1003.94 2263.78,1003.94 3316.93,1003.94 4125.98,1003.94 4763.78,1003.94 4763.78,683.07 4763.78,-383.86 4763.78,-1003.94 4153.54,-1003.94 2263.78,-1003.94

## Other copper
Top Layer:
  text "380_HV" at 4297.24,-807.09 h60
Bottom Layer:
  text "380_HV" at 4637.8,-688.98 h60

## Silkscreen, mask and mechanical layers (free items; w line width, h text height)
Top Solder:
  text "380_CTRL" at 456.69,-618.11 h55.12 r90
Bottom Solder:
  text "380_CTRL" at 62.99,-332.68 h60 r270
Mechanical 1:
  lines w3.94: -59.06,-944.88 572.83,-944.88 ; -59.06,948.82 972.44,948.82 ; 206.69,-834.65 411.42,-834.65 ; 240.16,838.58 411.42,838.58 ; 354.33,-984.25 354.33,996.06 ; 1263.78,889.76 2062.99,889.76 ; 1379.92,-590.55 2074.8,-590.55 ; 1574.8,-830.71 1574.8,988.19
  lines w7.87: 3000,1003.94 3000,984.25 3047.24,984.25 3047.24,1003.94 ; 3019.69,-1001.97 3019.69,-982.28 3066.93,-982.28 3066.93,-1001.97
  lines w19.68: -59.06,-1003.94 -59.06,1003.94 ; 2350.39,0 2401.57,0
  text "42,2" at 255.91,-122.05 h60 r90

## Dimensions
-177.17,1003.94 to -59.06,1003.94 on Mechanical 1
-59.06,1003.94 to 354.33,996.06 on Mechanical 1
-59.06,1003.94 to 2066.93,1003.94 on Mechanical 1
-59.06,1003.94 to 311.02,744.09 on Mechanical 1
-59.06,-1003.94 to 783.46,-271.65 on Mechanical 1
1328.74,581.5 to 2066.93,1003.94 on Mechanical 1
1299.21,-469.68 to 2066.93,-1003.94 on Mechanical 1
1299.21,-469.68 to 1328.74,581.5 on Mechanical 1
1299.21,-469.68 to 2066.93,-1003.94 on Mechanical 1
1328.74,481.5 to 2066.93,1003.94 on Mechanical 1
783.46,-744.09 to 783.46,271.65 on Mechanical 1
-177.17,-1003.94 to 783.46,-271.65 on Mechanical 1
783.46,744.09 to -177.17,1003.94 on Mechanical 1
1574.8,988.19 to 2066.93,-1003.94 on Mechanical 1
2066.93,-1003.94 to 1379.92,-590.55 on Mechanical 1
2066.93,1003.94 to 2062.99,889.76 on Mechanical 1
206.69,-834.65 to 240.16,838.58 on Mechanical 1
-59.06,-944.88 to -177.17,-1003.94 on Mechanical 1
-59.06,948.82 to -177.17,1003.94 on Mechanical 1
2066.93,-1003.94 to 2066.93,1003.94 on Mechanical 1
